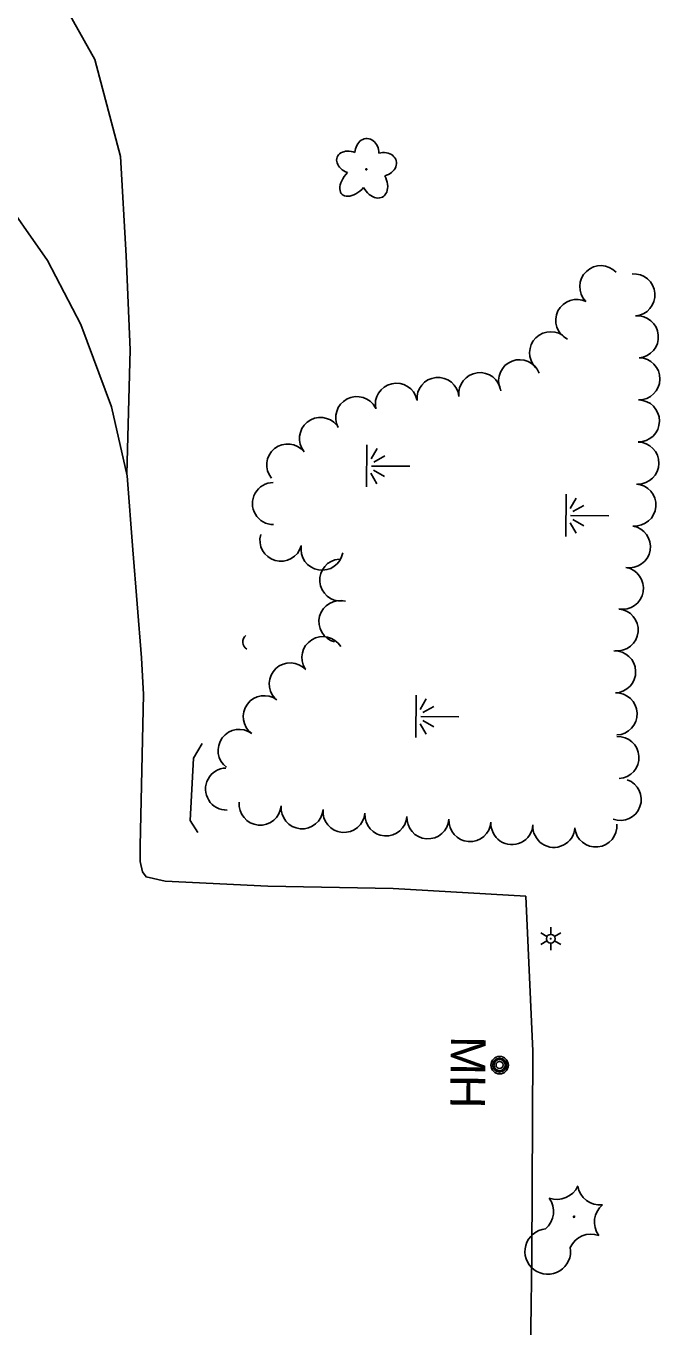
# Model space of a CAD drawing. Extents: x 588843 to 2552415, y 180129 to 269402.
# Drawn here: x 593672.1 to 593781.5, y 186471.7 to 186696.3 of the extents above; entities that cross this region are included whole.
import ezdxf

# ---------------------------------------------------------------- set-up
doc = ezdxf.new("R2010")
doc.units = 0
for name, color, linetype in [('Default', 7, 'Continuous'), ('E_DRN', 7, 'Continuous'), ('E_DWY', 7, 'Continuous'), ('E_LAND_TreeLine_P', 7, 'Continuous'), ('E_LAND_Vegetation', 7, 'Continuous'), ('E_LTG', 7, 'Continuous'), ('E_STRUCT', 7, 'Continuous'), ('E_UTL_MH', 7, 'Continuous'), ('E_UTL_MH_Text', 7, 'Continuous'), ('E_WTR_Wetland', 7, 'Continuous')]:
    doc.layers.add(name, color=color, linetype=linetype)

# ---------------------------------------------------------------- blocks, each defined once
blk = doc.blocks.new('LPOL')
at = {"layer": 'Default'}
for p, q in [((-4, 0), (-1.5, 0)), ((-0.75, 1.3), (-2, 3.46)), ((0.75, 1.3), (2, 3.46)), ((1.5, 0), (4, 0)), ((-2, -3.46), (-0.75, -1.3)), ((2, -3.46), (0.75, -1.3))]:
    blk.add_line(p, q, dxfattribs=at)
for radius in [1.5, 1.5, 1.5, 0.125]:
    blk.add_circle((0, 0), radius, dxfattribs=at)
blk = doc.blocks.new('CTRE')
at = {"layer": 'Default'}
blk.add_circle((0, 0), 0.223, dxfattribs=at)
for centre, start, end in [((-11.97, 8.96), 280.2067, 5.9716), ((1.81, 14.92), 220.2113, 305.9762), ((13.83, 5.89), 160.2113, 245.9762), ((-13.83, -5.9), 340.2113, 65.9762), ((12.03, -9.04), 185.9272, 100.2511), ((-1.81, -14.93), 40.2113, 125.9762)]:
    blk.add_arc(centre, 7.87, start, end, dxfattribs=at)
blk = doc.blocks.new('MHT')
at = {"layer": 'E_UTL_MH_Text'}
blk.add_text('MH', height=12, dxfattribs=at).set_placement((-9.81, -6))
blk = doc.blocks.new('MHO')
at = {"layer": 'Default'}
for centre, radius in [((0.08, -0.12), 3), ((0.08, -0.12), 2.43), ((0.07, -0.15), 1.94), ((0.02, -0.16), 1.21)]:
    blk.add_circle(centre, radius, dxfattribs=at)
blk = doc.blocks.new('CULV2')
at = {"layer": 'E_DRN'}
blk.add_arc((19.7, 14.8), 24.6, 216.8699, 323.1301, dxfattribs=at)
blk = doc.blocks.new('DTRE')
at = {"layer": 'Default'}
blk.add_circle((-0.18, 0), 0.183, dxfattribs=at)
for centre, major_axis, ratio in [((-1.87, 5.32), (1.36, -4.98), 0.782863), ((4.06, 2.74), (-5.27, -2.93), 0.691916), ((-5.87, 0.15), (4.93, -0.12), 0.832022), ((-2.49, -5.24), (1.8, 4.86), 0.716896), ((3.54, -3.71), (-5.01, 4.58), 0.560249)]:
    blk.add_ellipse(centre, major_axis=major_axis, ratio=ratio, start_param=1.570796, end_param=4.712389, dxfattribs=at)
blk = doc.blocks.new('MAR')
at = {"layer": 'Default'}
for p, q in [((-0.02, 14.83), (-0.02, 1.62)), ((-1.37, 2.38), (-3.54, 6.17)), ((1.39, 2.38), (3.55, 6.17)), ((-7.33, 0), (7.23, 0)), ((-6.08, 3.52), (-2.46, 1.46)), ((6.1, 3.52), (2.47, 1.46))]:
    blk.add_line(p, q, dxfattribs=at)

msp = doc.modelspace()

# ---------------------------------------------------------------- linework, layer by layer
at = {"layer": 'E_DWY'}
for points in [[(593591.77, 186720.72), (593593.36, 186722.65), (593597.85, 186719.78), (593603.23, 186716.86), (593610.4, 186714.07), (593608.97, 186710.3), (593607.96, 186704.52), (593631.13, 186696.7), (593643.55, 186689.9), (593656.66, 186678.88), (593667.04, 186668.23), (593675.78, 186655.81), (593681.53, 186644.73), (593686.85, 186630.53), (593689.52, 186618.63), (593690.53, 186605.83), (593692.03, 186587.19), (593692.36, 186580.89), (593691.77, 186554.75), (593691.75, 186552.08)], [(593689.46, 186618.9), (593690.05, 186640.35), (593689.39, 186656.62), (593688.37, 186673.75), (593683.95, 186690.5), (593678.43, 186700.33)], [(593691.75, 186552.08), (593692.17, 186550.27), (593692.81, 186549.4), (593696.11, 186548.65), (593713.81, 186547.81), (593735.44, 186547.41), (593758.31, 186546.06), (593759.53, 186519.34), (593759.38, 186483.93), (593758.86, 186446.35), (593758.89, 186410.14), (593759.07, 186363.78), (593758.91, 186319.14), (593758.71, 186277.58), (593758.99, 186233.19), (593758.98, 186173.88), (593758.89, 186133.64), (593758.82, 186113.71)]]:
    msp.add_lwpolyline(points, dxfattribs=at)
at = {"layer": 'E_LAND_TreeLine_P'}
for centre, start, end in [((593771.27, 186651.28), 43.522, 223.522), ((593776.98, 186649.85), 274.6697, 94.6697), ((593767.12, 186645.45), 63.3681, 243.3681), ((593777.57, 186642.61), 274.6697, 94.6697), ((593762.61, 186639.87), 44.4284, 224.4284), ((593757.26, 186635.04), 21.2362, 201.2362), ((593777.84, 186635.36), 269.2586, 89.2586), ((593743.17, 186631.98), 5.6503, 185.6503), ((593750.39, 186632.82), 7.1119, 187.1119), ((593735.99, 186630.99), 12.9564, 192.9564), ((593729.17, 186628.68), 27.8349, 207.8349), ((593777.75, 186628.1), 269.2586, 89.2586), ((593722.89, 186625.07), 38.9719, 218.9719), ((593717.24, 186620.5), 38.9719, 218.9719), ((593777.66, 186620.83), 269.2586, 89.2586), ((593714.78, 186613.84), 90.4834, 270.4834), ((593777.14, 186613.59), 265.8121, 85.8121), ((593716.07, 186607.52), 164.2452, 344.2452), ((593776.21, 186606.39), 260.3841, 80.3841), ((593723.16, 186605.97), 170.3512, 350.3512), ((593726.4, 186600.65), 94.8751, 274.8751), ((593775, 186599.23), 260.3841, 80.3841), ((593726.26, 186593.48), 75.1332, 255.1332), ((593774.08, 186592.03), 264.8412, 84.8412), ((593723.31, 186587.26), 32.1873, 212.1873), ((593773.65, 186584.79), 271.9495, 91.9495), ((593717.68, 186582.72), 42.9636, 222.9636), ((593713.19, 186577.06), 53.2829, 233.2829), ((593773.9, 186577.54), 271.9495, 91.9495), ((593708.85, 186571.24), 53.2829, 233.2829), ((593774.23, 186570.02), 273.2683, 93.2683), ((593706.69, 186564.57), 91.7026, 271.7026), ((593774.61, 186562.77), 250.2508, 70.2508), ((593712.48, 186561.97), 175.0155, 355.0155), ((593719.72, 186561.34), 175.0155, 355.0155), ((593726.95, 186560.71), 175.0155, 355.0155), ((593734.19, 186560.11), 176.0886, 356.0886), ((593741.43, 186559.61), 176.0886, 356.0886), ((593748.68, 186559.12), 176.0886, 356.0886), ((593755.93, 186558.62), 176.0939, 356.0939), ((593763.17, 186558.13), 176.0939, 356.0939), ((593770.41, 186558.19), 185.3807, 5.3807)]:
    msp.add_arc(centre, 3.63, start, end, dxfattribs=at)
at = {"layer": 'E_STRUCT'}
msp.add_lwpolyline([(593702.5, 186572.45), (593700.99, 186569.89), (593700.42, 186559.16), (593701.74, 186557.07)], dxfattribs=at)

# ---------------------------------------------------------------- block references
at = {"layer": 'E_DRN', "xscale": 0.060918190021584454, "yscale": 0.06091819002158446, "rotation": -85.62904440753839}
msp.add_blockref('CULV2', (593710, 186591.1), dxfattribs=at)
at = {"layer": 'E_LAND_Vegetation'}
for name, p, xscale, yscale, rotation in [('DTRE', (593730.8, 186671.43), 0.5, 0.5, -90.39883281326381), ('CTRE', (593766.65, 186490.76), 0.49999999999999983, 0.4999999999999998, -90.18477185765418)]:
    msp.add_blockref(name, p, dxfattribs=dict(at, xscale=xscale, yscale=yscale, rotation=rotation))
at = {"layer": 'E_LTG', "xscale": 0.49999999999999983, "yscale": 0.4999999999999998, "rotation": -90.18477185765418}
msp.add_blockref('LPOL', (593762.62, 186538.75), dxfattribs=at)
at = {"layer": 'E_UTL_MH', "xscale": 0.5, "yscale": 0.5, "rotation": -90.6534731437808}
msp.add_blockref('MHO', (593753.87, 186516.96), dxfattribs=at)
at = {"layer": 'E_UTL_MH_Text', "xscale": 0.5, "yscale": 0.5, "rotation": -90.6534731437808}
msp.add_blockref('MHT', (593748.35, 186517.02), dxfattribs=at)
at = {"layer": 'E_WTR_Wetland', "xscale": 0.5, "yscale": 0.5, "rotation": -90.39883281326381}
for p in [(593730.88, 186620.32), (593765.25, 186611.77), (593739.37, 186577.09)]:
    msp.add_blockref('MAR', p, dxfattribs=at)

doc.saveas('drawing.dxf')
